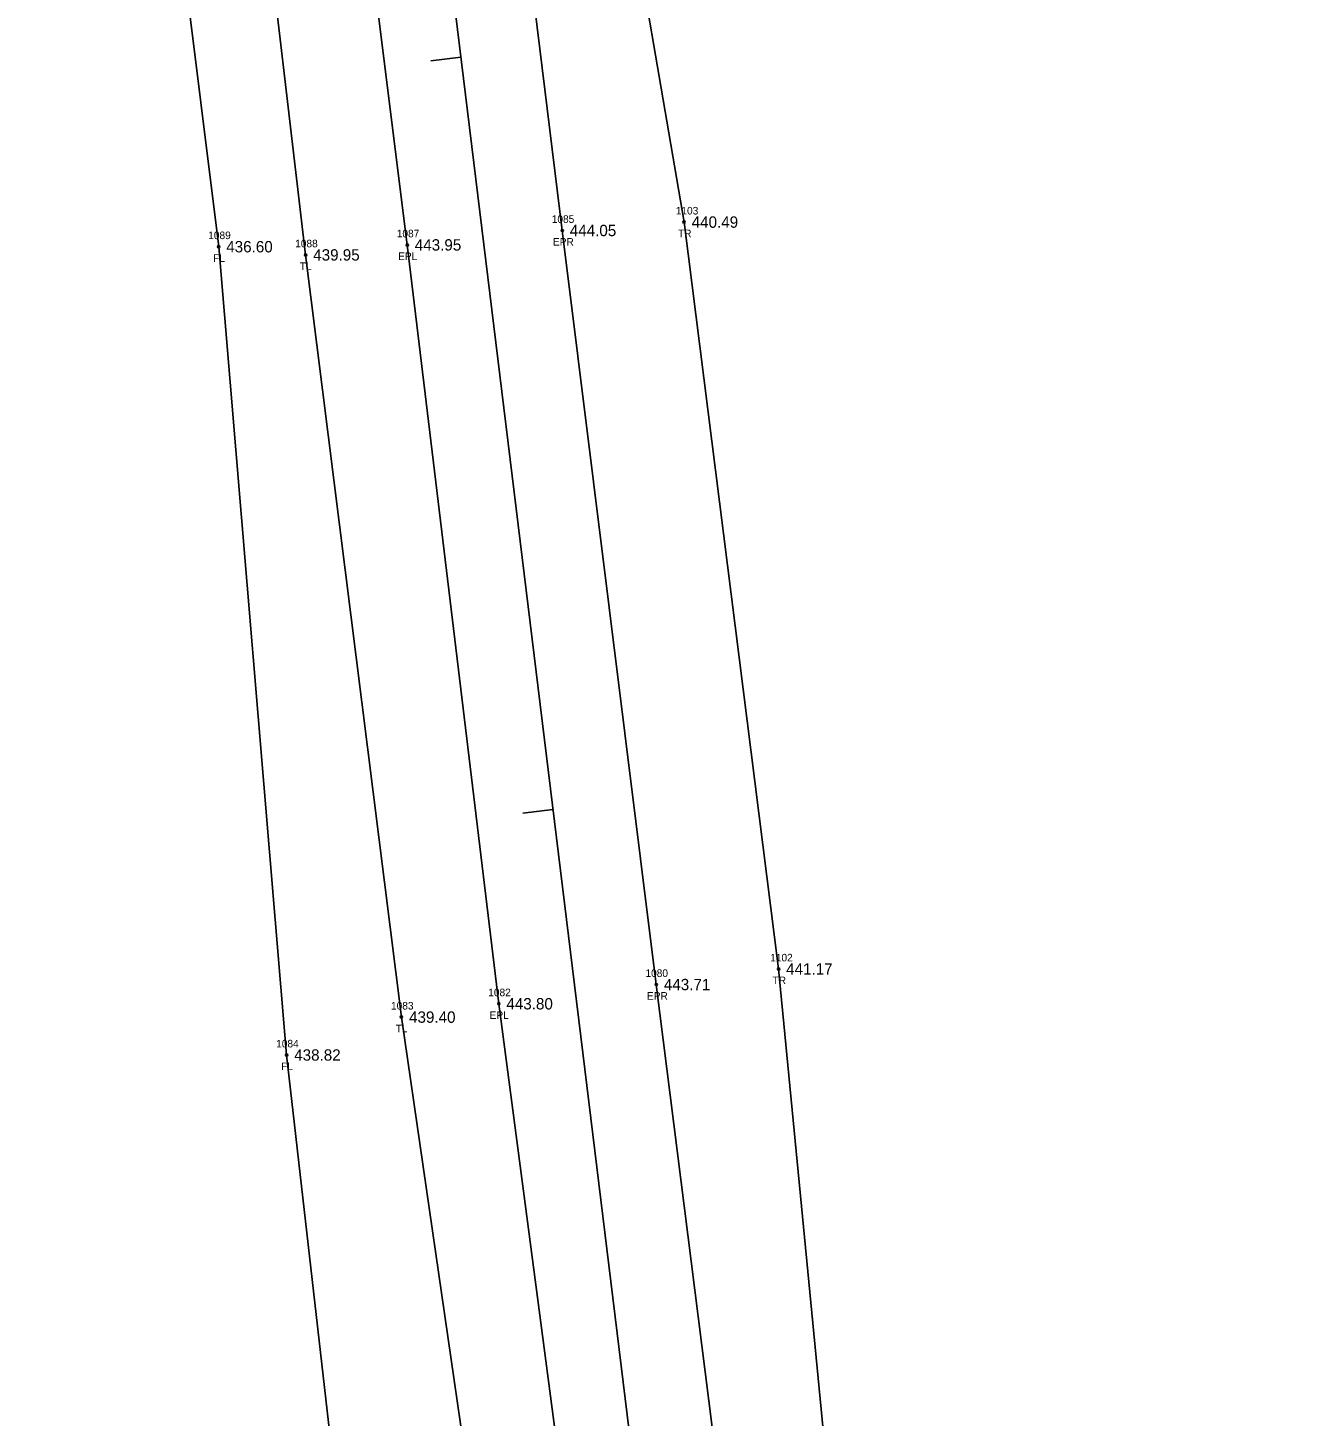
# Model space of a CAD drawing. Extents: x 1858454 to 1858924, y 1147053 to 1148170.
# Drawn here: x 1858581.8 to 1858751.6, y 1147803.4 to 1147986.7 of the extents above; entities that cross this region are included whole.
import ezdxf

# ---------------------------------------------------------------- set-up
doc = ezdxf.new("R2010")
doc.units = 0
for name, color, linetype in [('RD_EX_Fence_Other', 7, 'Continuous'), ('RD_EX_Fence_Other_txCode', 7, 'Continuous'), ('RD_EX_Road', 7, 'Continuous'), ('RD_EX_Road_txCode', 7, 'Continuous'), ('RD_EX_TX_Fence_Other_ELEV', 7, 'Continuous'), ('RD_EX_TX_Road_ELEV', 7, 'Continuous'), ('RD_EX_TX_VEG_ELEV', 7, 'Continuous'), ('RD_EX_VEG', 7, 'Continuous'), ('RD_EX_VEG_txCode', 7, 'Continuous'), ('RD_HC_Cl', 7, 'Continuous'), ('RD_HC_Data_Tic', 7, 'Continuous'), ('RD_SMD_Locator', 7, 'Continuous')]:
    doc.layers.add(name, color=color, linetype=linetype)

msp = doc.modelspace()

# ---------------------------------------------------------------- linework, layer by layer
at = {"layer": 'RD_EX_Fence_Other'}
msp.add_lwpolyline([(1858628.27, 1147625.58), (1858627.01, 1147754.05), (1858615.95, 1147851.08), (1858606.98, 1147957.76), (1858595.17, 1148052.68), (1858581.78, 1148154.12)], dxfattribs=at)
at = {"layer": 'RD_EX_Road'}
for points in [[(1858679.02, 1147660.19), (1858688.73, 1147661.54), (1858677.21, 1147761.6), (1858664.75, 1147860.38), (1858652.33, 1147959.9), (1858640.18, 1148058.71), (1858627.63, 1148158.94)], [(1858679.02, 1147660.19), (1858669.49, 1147658.82), (1858657, 1147758.92), (1858643.96, 1147857.84), (1858631.87, 1147958), (1858619.69, 1148055.49), (1858606.59, 1148156.75)]]:
    msp.add_lwpolyline(points, dxfattribs=at)
at = {"layer": 'RD_EX_VEG'}
for points in [[(1858786.58, 1147073.62), (1858775.98, 1147174.64), (1858762.89, 1147274.03), (1858752.24, 1147373.24), (1858736.96, 1147479.89), (1858729.06, 1147571.9), (1858711.6, 1147670.3), (1858690.41, 1147764.38), (1858680.89, 1147862.43), (1858668.42, 1147961.01), (1858651.26, 1148061.01), (1858641.53, 1148160.37)], [(1858726.29, 1147071.02), (1858708.41, 1147166.41), (1858698.92, 1147264.27), (1858694.52, 1147368.74), (1858682.22, 1147467.57), (1858636.43, 1147636.58), (1858645.41, 1147757.54), (1858631.11, 1147856.08), (1858618.46, 1147956.68), (1858606.82, 1148055.62), (1858592.91, 1148154.69)]]:
    msp.add_lwpolyline(points, dxfattribs=at)
at = {"layer": 'RD_HC_Cl'}
msp.add_line((1858750.25, 1147074.55), (1858617.68, 1148156.23), dxfattribs=at)
at = {"layer": 'RD_HC_Data_Tic'}
for p, q in [((1858638.94, 1147982.76), (1858634.97, 1147982.27)), ((1858651.1, 1147883.5), (1858647.13, 1147883.01))]:
    msp.add_line(p, q, dxfattribs=at)
at = {"layer": 'RD_SMD_Locator'}
for centre in [(1858668.42, 1147961.01), (1858652.33, 1147959.9), (1858606.98, 1147957.76), (1858618.46, 1147956.68), (1858631.87, 1147958), (1858680.89, 1147862.43), (1858664.75, 1147860.38), (1858643.96, 1147857.84), (1858631.11, 1147856.08), (1858615.95, 1147851.08)]:
    msp.add_circle(centre, 0.15, dxfattribs=at)

# ---------------------------------------------------------------- texts
at = {"layer": 'RD_EX_Fence_Other_txCode'}
for s, p in [('1089', (1858605.6, 1147958.76)), ('FL', (1858606.25, 1147955.76)), ('1084', (1858614.57, 1147852.08)), ('FL', (1858615.22, 1147849.08))]:
    msp.add_text(s, height=1, dxfattribs=at).set_placement(p)
at = {"layer": 'RD_EX_Road_txCode'}
for s, p in [('1085', (1858650.95, 1147960.9)), ('1087', (1858630.49, 1147959)), ('EPR', (1858651.11, 1147957.9)), ('EPL', (1858630.67, 1147956)), ('1080', (1858663.32, 1147861.38)), ('1082', (1858642.57, 1147858.84)), ('EPR', (1858663.52, 1147858.38)), ('EPL', (1858642.75, 1147855.84))]:
    msp.add_text(s, height=1, dxfattribs=at).set_placement(p)
at = {"layer": 'RD_EX_TX_Fence_Other_ELEV'}
for s, p in [('436.60', (1858607.98, 1147957.01)), ('438.82', (1858616.95, 1147850.33))]:
    msp.add_text(s, height=1.5, dxfattribs=at).set_placement(p)
at = {"layer": 'RD_EX_TX_Road_ELEV'}
for s, p in [('444.05', (1858653.33, 1147959.15)), ('443.95', (1858632.87, 1147957.25)), ('443.71', (1858665.75, 1147859.63)), ('443.80', (1858644.96, 1147857.09))]:
    msp.add_text(s, height=1.5, dxfattribs=at).set_placement(p)
at = {"layer": 'RD_EX_TX_VEG_ELEV'}
for s, p in [('440.49', (1858669.42, 1147960.26)), ('439.95', (1858619.46, 1147955.93)), ('441.17', (1858681.89, 1147861.68)), ('439.40', (1858632.11, 1147855.33))]:
    msp.add_text(s, height=1.5, dxfattribs=at).set_placement(p)
at = {"layer": 'RD_EX_VEG_txCode'}
for s, p in [('1103', (1858667.32, 1147962.01)), ('1088', (1858617.08, 1147957.68)), ('TR', (1858667.62, 1147959.01)), ('TL', (1858617.69, 1147954.68)), ('1102', (1858679.79, 1147863.43)), ('TR', (1858680.1, 1147860.43)), ('1083', (1858629.73, 1147857.08)), ('TL', (1858630.34, 1147854.08))]:
    msp.add_text(s, height=1, dxfattribs=at).set_placement(p)

doc.saveas('drawing.dxf')
